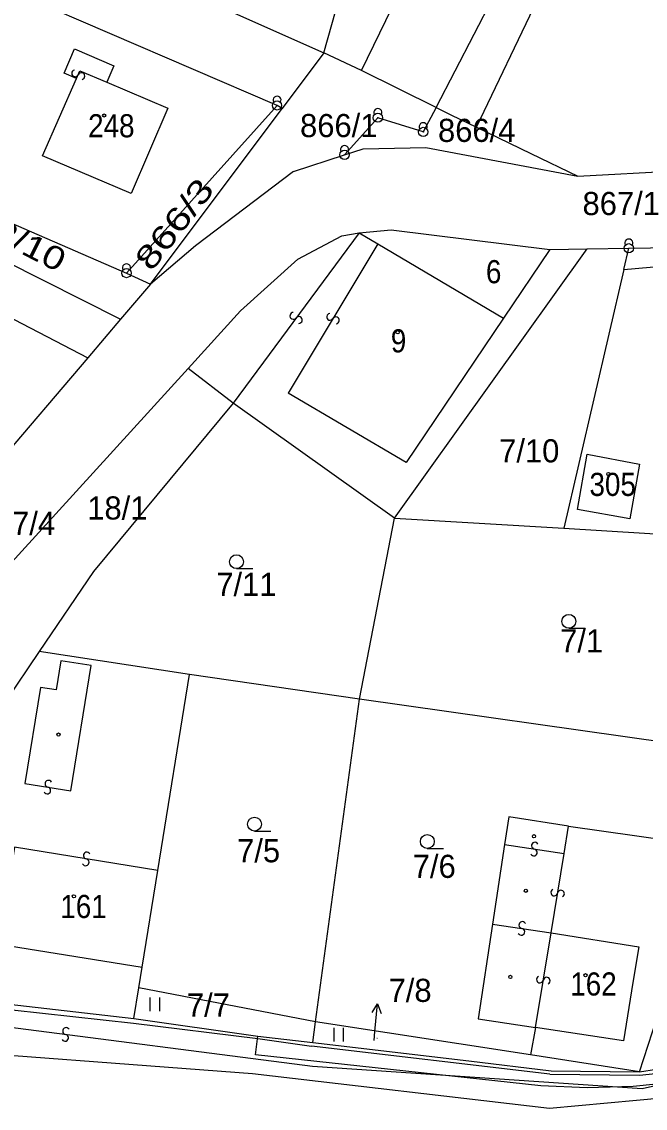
# Model space of a CAD drawing. Extents: x -680102 to -677253, y -1007548 to -1006096.
# Drawn here: x -679670.3 to -679602.9, y -1007081 to -1006963.5 of the extents above; entities that cross this region are included whole.
import ezdxf
from ezdxf.enums import TextEntityAlignment as Align

# ---------------------------------------------------------------- set-up
doc = ezdxf.new("R2010")
doc.units = 0
for name, color, linetype, lineweight in [('1', 7, 'Continuous', 25), ('16', 7, 'Continuous', 25), ('24', 7, 'Continuous', 25), ('25', 7, 'Continuous', 25), ('4', 7, 'Continuous', 25)]:
    doc.layers.add(name, color=color, linetype=linetype, lineweight=lineweight)
doc.layers.add('18', color=7, linetype='Continuous')
doc.layers.add('19', color=7, linetype='Continuous')

msp = doc.modelspace()

# ---------------------------------------------------------------- linework, layer by layer
at = {"layer": '1'}
for p, q in [((-679625.54, -1006972.81), (-679615.15, -1006952.74)), ((-679642.75, -1006972.58), (-679678.38, -1006957.22)), ((-679648.66, -1006962.03), (-679637.68, -1006966.9)), ((-679642.75, -1006972.58), (-679659.02, -1006990.71)), ((-679656.42, -1006991.92), (-679642.18, -1006972.9)), ((-679625.54, -1006972.81), (-679623.97, -1006973.59)), ((-679709.44, -1006975.78), (-679663.2, -1006999.87)), ((-679615.3, -1006977.78), (-679610.24, -1006980.22)), ((-679640.97, -1006979.72), (-679651.57, -1006987.75)), ((-679633.87, -1006986.36), (-679630.4, -1006986.05)), ((-679633.87, -1006986.36), (-679631.86, -1006987.56)), ((-679630.4, -1006986.05), (-679613.28, -1006988.17)), ((-679651.57, -1006987.75), (-679656.42, -1006991.92)), ((-679631.86, -1006987.56), (-679618.27, -1006995.58)), ((-679630.04, -1007017.2), (-679609.23, -1006988.1)), ((-679613.28, -1006988.17), (-679618.27, -1006995.58)), ((-679613.28, -1006988.17), (-679609.23, -1006988.1)), ((-679605.27, -1006990.34), (-679604.73, -1006988.03)), ((-679646.69, -1006994.81), (-679640.49, -1006989.19)), ((-679659.02, -1006990.71), (-679656.42, -1006991.92)), ((-679656.42, -1006991.92), (-679659.65, -1006995.68)), ((-679659.65, -1006995.68), (-679663.2, -1006999.87)), ((-679663.2, -1006999.87), (-679677.08, -1007016.16)), ((-679647.5, -1007004.77), (-679652.35, -1007001.03)), ((-679647.5, -1007004.77), (-679662.59, -1007022.98)), ((-679630.04, -1007017.2), (-679647.5, -1007004.77)), ((-679633.83, -1007036.77), (-679630.04, -1007017.2)), ((-679630.04, -1007017.2), (-679611.75, -1007018.31)), ((-679652.2, -1007034.11), (-679668.44, -1007031.62)), ((-679655.63, -1007055.32), (-679652.2, -1007034.11)), ((-679633.83, -1007036.77), (-679652.2, -1007034.11)), ((-679638.59, -1007071.68), (-679633.83, -1007036.77)), ((-679593.1, -1007042.56), (-679633.83, -1007036.77)), ((-679611.26, -1007050.51), (-679595.71, -1007052.73)), ((-679603.56, -1007077.07), (-679595.71, -1007052.73)), ((-679657.32, -1007065.78), (-679655.63, -1007055.32)), ((-679657.69, -1007068), (-679657.32, -1007065.78)), ((-679658.21, -1007071.31), (-679657.69, -1007068)), ((-679638.59, -1007071.68), (-679657.69, -1007068)), ((-679676.67, -1007069.21), (-679658.21, -1007071.31)), ((-679658.21, -1007071.31), (-679644.83, -1007073.22)), ((-679638.88, -1007073.91), (-679638.59, -1007071.68)), ((-679615.34, -1007075.23), (-679638.59, -1007071.68)), ((-679614.83, -1007072.28), (-679615.34, -1007075.23)), ((-679603.56, -1007077.07), (-679615.34, -1007075.23))]:
    msp.add_line(p, q, dxfattribs=at)
for points in [[(-679637.68, -1006966.9), (-679629.53, -1006937.87), (-679640.64, -1006933.79)], [(-679633.62, -1006968.81), (-679623.75, -1006948.48), (-679622.12, -1006945.13)], [(-679621.19, -1006974.93), (-679614.59, -1006961.14), (-679613.4, -1006961.21), (-679612.53, -1006961.58), (-679610.06, -1006955.38)], [(-679712.27, -1006964.85), (-679687.2, -1006977.42), (-679687.64, -1006978.29), (-679659.02, -1006990.71)], [(-679718.34, -1006966.18), (-679713.82, -1006968.45), (-679688.93, -1006980.96), (-679659.65, -1006995.68)], [(-679637.68, -1006966.9), (-679642.18, -1006972.9), (-679642.75, -1006972.58)], [(-679625.54, -1006972.81), (-679633.62, -1006968.81), (-679637.68, -1006966.9)], [(-679625.54, -1006972.81), (-679626.95, -1006975.45), (-679631.85, -1006973.91), (-679635.45, -1006977.92)], [(-679623.97, -1006973.59), (-679621.19, -1006974.93), (-679615.3, -1006977.78)], [(-679610.24, -1006980.22), (-679588.99, -1006979.09), (-679579.98, -1006973.93)], [(-679640.97, -1006979.72), (-679635.45, -1006977.92), (-679633.43, -1006977.27)], [(-679633.43, -1006977.27), (-679626.65, -1006977.15), (-679610.24, -1006980.22)], [(-679640.49, -1006989.19), (-679635.74, -1006986.7), (-679633.87, -1006986.36)], [(-679609.23, -1006988.1), (-679604.73, -1006988.03), (-679583.59, -1006987.69), (-679579.65, -1006987.63)], [(-679605.27, -1006990.34), (-679583.74, -1006988.4), (-679590.25, -1007019.62), (-679586.29, -1007019.86)], [(-679605.27, -1006990.34), (-679611.75, -1007018.31), (-679590.25, -1007019.62)], [(-679678.79, -1007030.04), (-679652.35, -1007001.03), (-679646.69, -1006994.81)], [(-679662.59, -1007022.98), (-679668.44, -1007031.62), (-679672.09, -1007037.02), (-679671.26, -1007031.19)], [(-679611.26, -1007050.51), (-679617.69, -1007049.52), (-679618.15, -1007052.51), (-679619.46, -1007061.1), (-679621.02, -1007071.34), (-679614.83, -1007072.28)], [(-679599.28, -1007078.15), (-679604.24, -1007078.68), (-679609.24, -1007078.8), (-679614.25, -1007078.59), (-679645.06, -1007075.26), (-679644.83, -1007073.22)], [(-679644.83, -1007073.22), (-679638.88, -1007073.91), (-679622.01, -1007075.9), (-679613.12, -1007076.97), (-679603.56, -1007077.07), (-679599.91, -1007076.52), (-679598.16, -1007076.05)]]:
    msp.add_lwpolyline(points, dxfattribs=at)
for points in [[(-679664.65, -1006966.47), (-679660.4, -1006968.29), (-679661.16, -1006970.06), (-679654.56, -1006972.88), (-679658.5, -1006982.11), (-679668.11, -1006978.03), (-679664.42, -1006969.68), (-679665.77, -1006969.1)], [(-679609.22, -1007010.3), (-679603.59, -1007011.39), (-679604.62, -1007017.29), (-679610.29, -1007016.27)]]:
    msp.add_lwpolyline(points, close=True, dxfattribs=at)
at = {"layer": '16'}
for p, q in [((-679632.17, -1007072.71), (-679631.888, -1007069.724)), ((-679632.26, -1007073.68), (-679632.17, -1007072.71))]:
    msp.add_line(p, q, dxfattribs=at)
msp.add_lwpolyline([(-679632.479, -1007070.672), (-679631.888, -1007069.724), (-679631.485, -1007070.766)], dxfattribs=at)
at = {"layer": '24'}
for centre, radius in [((-679642.75, -1006972.58), 0.5), ((-679642.75, -1006972.58), 0.022), ((-679631.85, -1006973.91), 0.5), ((-679631.85, -1006973.91), 0.022), ((-679626.95, -1006975.45), 0.5), ((-679626.95, -1006975.45), 0.022), ((-679635.45, -1006977.92), 0.5), ((-679635.45, -1006977.92), 0.022), ((-679604.73, -1006988.03), 0.5), ((-679604.73, -1006988.03), 0.022), ((-679659.02, -1006990.71), 0.5), ((-679659.02, -1006990.71), 0.022)]:
    msp.add_circle(centre, radius, dxfattribs=at)
for centre in [(-679642.751, -1006972.017), (-679631.851, -1006973.347), (-679626.951, -1006974.887), (-679635.451, -1006977.357), (-679604.731, -1006987.467), (-679659.021, -1006990.147)]:
    msp.add_arc(centre, 0.437, 328.35109, 209.97456, dxfattribs=at)
at = {"layer": '25'}
for p, q in [((-679647.13, -1007022.67), (-679645.38, -1007022.67)), ((-679611.21, -1007029.12), (-679609.46, -1007029.12)), ((-679645.18, -1007051.04), (-679643.43, -1007051.04)), ((-679626.51, -1007052.92), (-679624.76, -1007052.92)), ((-679656.457, -1007070.535), (-679656.457, -1007069.035)), ((-679655.423, -1007070.535), (-679655.423, -1007069.035)), ((-679636.587, -1007073.815), (-679636.587, -1007072.315)), ((-679635.553, -1007073.815), (-679635.553, -1007072.315))]:
    msp.add_line(p, q, dxfattribs=at)
for centre, radius in [((-679661.43, -1006973.67), 0.175), ((-679629.71, -1006997.11), 0.175), ((-679606.94, -1007012.45), 0.175), ((-679647.13, -1007021.92), 0.75), ((-679611.21, -1007028.37), 0.75), ((-679666.37, -1007040.61), 0.175), ((-679645.18, -1007050.29), 0.75), ((-679626.51, -1007052.17), 0.75), ((-679614.98, -1007051.61), 0.175), ((-679664.7, -1007058.1), 0.175), ((-679615.86, -1007057.5), 0.175), ((-679617.53, -1007066.82), 0.175), ((-679609.41, -1007066.64), 0.175)]:
    msp.add_circle(centre, radius, dxfattribs=at)
for centre, radius, start, end in [((-679664.566, -1006969.111), 0.367, 104.05256, 336.08767), ((-679663.894, -1006969.411), 0.368, 283.81233, 155.80472), ((-679640.983, -1006995.337), 0.369, 90.62179, 322.60279), ((-679640.397, -1006995.781), 0.367, 270.45414, 142.97512), ((-679637.014, -1006995.437), 0.368, 96.3925, 328.18952), ((-679636.386, -1006995.822), 0.368, 276.25085, 148.55686), ((-679667.582, -1007046.653), 0.368, 208.16557, 80.31098), ((-679667.459, -1007045.928), 0.367, 28.1774, 260.43711), ((-679614.883, -1007052.627), 0.367, 28.76031, 261.07809), ((-679663.307, -1007053.697), 0.368, 28.16414, 259.92957), ((-679614.998, -1007053.354), 0.368, 208.8601, 80.78965), ((-679663.432, -1007054.422), 0.367, 207.93256, 80.28185), ((-679612.782, -1007057.689), 0.367, 118.37825, 350.43783), ((-679612.057, -1007057.812), 0.368, 298.16628, 170.47502), ((-679616.348, -1007061.934), 0.368, 208.8601, 80.78965), ((-679616.233, -1007061.207), 0.367, 28.76031, 261.07809), ((-679614.332, -1007067.096), 0.367, 117.98899, 349.97675), ((-679613.607, -1007067.226), 0.368, 297.68117, 169.92437), ((-679665.55, -1007072.666), 0.367, 30.06781, 262.18073), ((-679665.651, -1007073.395), 0.368, 209.97812, 81.89314)]:
    msp.add_arc(centre, radius, start, end, dxfattribs=at)
at = {"layer": '4'}
for p, q in [((-679633.87, -1006986.36), (-679647.5, -1007004.77)), ((-679631.86, -1006987.56), (-679641.54, -1007003.7)), ((-679618.27, -1006995.58), (-679628.79, -1007011.21)), ((-679628.79, -1007011.21), (-679641.54, -1007003.7)), ((-679666.11, -1007032.63), (-679666.62, -1007035.79)), ((-679668.3, -1007035.51), (-679669.99, -1007045.89)), ((-679666.62, -1007035.79), (-679668.3, -1007035.51)), ((-679618.15, -1007052.51), (-679611.73, -1007053.46)), ((-679619.46, -1007061.1), (-679613.11, -1007062.04)), ((-679614.83, -1007072.28), (-679613.11, -1007062.04)), ((-679613.11, -1007062.04), (-679603.66, -1007063.55)), ((-679692.29, -1007069.6), (-679638.92, -1007076.45)), ((-679658.25, -1007071.8), (-679644.83, -1007073.47)), ((-679605.29, -1007073.74), (-679614.83, -1007072.28)), ((-679644.83, -1007073.47), (-679639.01, -1007074.32)), ((-679613.25, -1007077.35), (-679639.01, -1007074.32)), ((-679603.57, -1007077.43), (-679600.48, -1007077.13)), ((-679613.25, -1007077.35), (-679603.57, -1007077.43))]:
    msp.add_line(p, q, dxfattribs=at)
for points in [[(-679664.42, -1006969.68), (-679664.05, -1006968.83), (-679661.16, -1006970.06)], [(-679669.99, -1007045.89), (-679665.05, -1007046.69), (-679662.85, -1007033.16), (-679666.11, -1007032.63)], [(-679613.11, -1007062.04), (-679611.73, -1007053.46), (-679611.26, -1007050.51)], [(-679655.63, -1007055.32), (-679671.11, -1007052.8), (-679672.81, -1007063.27), (-679657.32, -1007065.78)], [(-679603.66, -1007063.55), (-679604.28, -1007067.41), (-679605.29, -1007073.74)], [(-679703.02, -1007069.54), (-679691.07, -1007068.22), (-679658.25, -1007071.8)], [(-679684.6, -1007074.32), (-679645.4, -1007077.27), (-679613.29, -1007081.02)], [(-679638.92, -1007076.45), (-679603.3, -1007078.87), (-679601.83, -1007078.57)], [(-679613.29, -1007081.02), (-679603.88, -1007080.15), (-679598.8, -1007079.68)]]:
    msp.add_lwpolyline(points, dxfattribs=at)

# ---------------------------------------------------------------- texts
at = {"layer": '16'}
for s, p in [('867/4', (-679675.1, -1007019.02)), ('7/8', (-679630.69, -1007069.52))]:
    msp.add_text(s, height=2.5, dxfattribs=at).set_placement(p)
at = {"layer": '18'}
for s, height, p in [('866/1', 2.5, (-679640.26, -1006976.01)), ('866/4', 2.5, (-679625.35, -1006976.53)), ('867/1', 2.5, (-679609.73, -1006984.44)), ('7/10', 2.5, (-679618.74, -1007011.18)), ('18/1', 2.5, (-679663.26, -1007017.36)), ('7/11', 2.5, (-679649.31, -1007025.62)), ('7/1', 2.5, (-679612.15, -1007031.73)), ('7/5', 2.5, (-679647.06, -1007054.42)), ('7/6', 2.5, (-679628.08, -1007056.11)), ('7/7', 2.5, (-679652.49, -1007071.11)), ('7/8', 0.1, (-679632.06, -1007073.48))]:
    msp.add_text(s, height=height, dxfattribs=at).set_placement(p)
at = {"layer": '18', "width": 1.35}
msp.add_text('866/3', height=2.5, rotation=52.2, dxfattribs=at).set_placement((-679656.325, -1006990.64))
at = {"layer": '18', "width": 1.25}
msp.add_text('12/10', height=2.5, rotation=333.003, dxfattribs=at).set_placement((-679671.064, -1006988.285), align=Align.CENTER)
at = {"layer": '18', "width": 0.9}
msp.add_text('6', height=2.5, dxfattribs=at).set_placement((-679620.17, -1006991.81))
at = {"layer": '19', "width": 0.9}
for s, p in [('248', (-679663.17, -1006976.03)), ('9', (-679630.45, -1006999.29)), ('305', (-679608.98, -1007014.81)), ('161', (-679666.17, -1007060.45)), ('162', (-679611.06, -1007068.83))]:
    msp.add_text(s, height=2.5, dxfattribs=at).set_placement(p)

doc.saveas('drawing.dxf')
